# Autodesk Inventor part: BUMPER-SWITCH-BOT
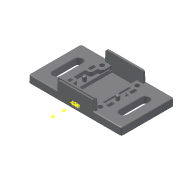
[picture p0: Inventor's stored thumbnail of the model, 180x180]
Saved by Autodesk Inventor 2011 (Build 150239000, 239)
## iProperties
Created: 2007-08
Part Number: BUMPER-SWITCH-BOT
Material: ABS Plastic
Document SubType Name: Modeling
Density: 1.06 g/cm^3
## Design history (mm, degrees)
feature "Base1"
sketch "Sketch1"
  geometry: L1 (15.459, 8.536)-(15.283, 3.509) reference; L2 (15.283, 3.509)-(0.061, 3.509) reference; L3 (0.061, 3.509)-(0, 0) reference; L4 (51, 0)-(0, 0) reference; L5 (51, 0)-(50.939, 3.509) reference; L6 (50.939, 3.509)-(35.717, 3.509) reference; L7 (35.717, 3.509)-(35.542, 8.536) reference; L8 (34.542, 9.501)-(16.458, 9.501) reference; L9 (22.45, 2.014)-(22.45, 2.814) reference; L10 (23.75, 4.115)-(27.25, 4.115) reference; L11 (28.55, 2.814)-(28.55, 2.014) reference; L12 (27.25, 0.714)-(23.75, 0.714) reference; L13 (22.45, 2.414)-(28.55, 2.414); L14 (27.75, 2.814)-(27.75, 2.014) reference; L15 (23.25, 2.014)-(23.25, 2.814) reference; 3 further points
  constraints: 3 point on line, 2 end point, 2 midpoint, 6 other
  dimensions: "d0" = 1.48938 distance of point (25.499, 2.414) point (24.009, 2.414); "d1" = 1.48938 distance of point (26.988, 2.414) point (25.499, 2.414) (= d0); "d2" = 0.762 distance from line of L14 point (26.988, 2.414)
node "1"
node "2"
node "3"
workplane "Work Plane1"
sketch "Sketch2"
  geometry: 1 further point
workplane "Work Plane2"
sketch "Sketch3"
  geometry: 1 further point
workpoint "Work Point4"
workpoint "Work Point5"
body "Solid1"
other parameters: "d3" = 6.35, "d4" = 6.35
